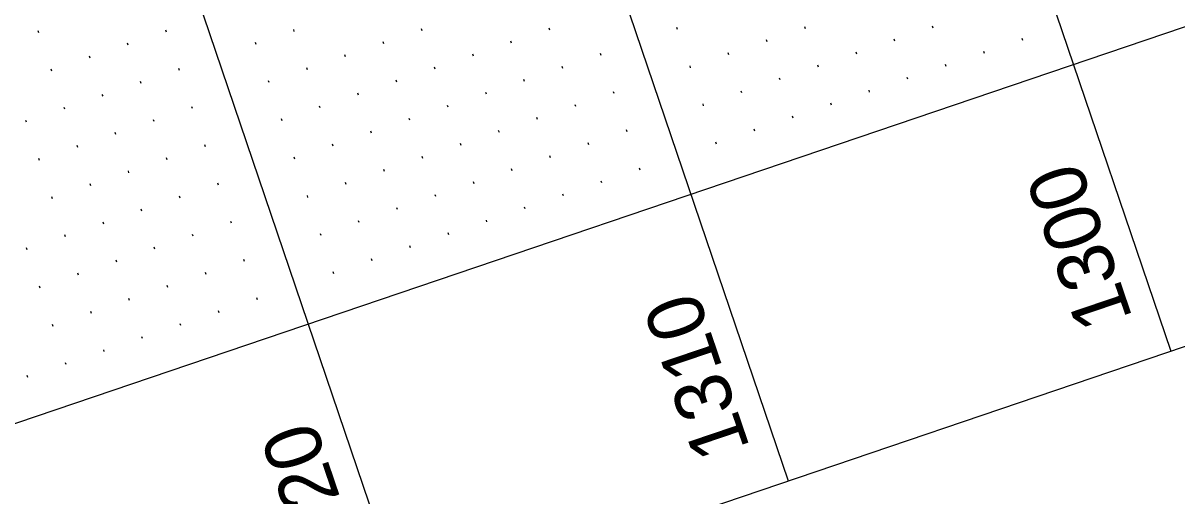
# Model space of a CAD drawing. Extents: x 2150800 to 2152547, y 141860 to 143950.
# Drawn here: x 2152030.1 to 2152172.8, y 142300.8 to 142359.4 of the extents above; entities that cross this region are included whole.
import ezdxf

# ---------------------------------------------------------------- set-up
doc = ezdxf.new("R2010")
doc.units = 0
for name, color, linetype in [('SHT_Plan_Profile_Sheet_Elev_Txt', 7, 'Continuous'), ('SHT_Profile_Grid_Major', 7, 'Continuous'), ('SHT_Profile_Grid_Minor', 7, 'Continuous'), ('SHT_Sheet_Border', 7, 'Continuous')]:
    doc.layers.add(name, color=color, linetype=linetype)

msp = doc.modelspace()

# ---------------------------------------------------------------- linework, layer by layer
at = {"layer": 'SHT_Profile_Grid_Major'}
for p, q in [((2152172.11, 142318.73), (2151666.12, 143810.24)), ((2152124.76, 142302.67), (2151618.77, 143794.18)), ((2152077.41, 142286.61), (2151571.42, 143778.12))]:
    msp.add_line(p, q, dxfattribs=at)
at = {"layer": 'SHT_Profile_Grid_Minor'}
for p, q in [((2152032.01, 142358.19), (2152031.93, 142358.43)), ((2152047.82, 142358.27), (2152047.74, 142358.51)), ((2152063.63, 142358.36), (2152063.55, 142358.59)), ((2152079.44, 142358.44), (2152079.36, 142358.68)), ((2152095.25, 142358.53), (2152095.17, 142358.76)), ((2152111.06, 142358.61), (2152110.98, 142358.85)), ((2152126.87, 142358.69), (2152126.79, 142358.93)), ((2152142.69, 142358.78), (2152142.61, 142359.01)), ((2152043.08, 142356.67), (2152043, 142356.9)), ((2152058.9, 142356.75), (2152058.81, 142356.99)), ((2152074.71, 142356.84), (2152074.63, 142357.07)), ((2152090.52, 142356.92), (2152090.44, 142357.16)), ((2152122.14, 142357.09), (2152122.06, 142357.32)), ((2152137.95, 142357.17), (2152137.87, 142357.41)), ((2152153.76, 142357.26), (2152153.68, 142357.49)), ((2152038.35, 142355.06), (2152038.27, 142355.3)), ((2152069.97, 142355.23), (2152069.89, 142355.47)), ((2152085.78, 142355.31), (2152085.7, 142355.55)), ((2152101.59, 142355.4), (2152101.51, 142355.63)), ((2152117.4, 142355.48), (2152117.32, 142355.72)), ((2152133.22, 142355.56), (2152133.14, 142355.8)), ((2152149.03, 142355.65), (2152148.95, 142355.89)), ((2152033.61, 142353.45), (2152033.53, 142353.69)), ((2152049.43, 142353.54), (2152049.34, 142353.78)), ((2152065.24, 142353.62), (2152065.16, 142353.86)), ((2152081.05, 142353.71), (2152080.97, 142353.94)), ((2152096.86, 142353.79), (2152096.78, 142354.03)), ((2152112.67, 142353.87), (2152112.59, 142354.11)), ((2152128.48, 142353.96), (2152128.4, 142354.2)), ((2152144.29, 142354.04), (2152144.21, 142354.28)), ((2152044.69, 142351.93), (2152044.61, 142352.17)), ((2152060.5, 142352.02), (2152060.42, 142352.25)), ((2152076.31, 142352.1), (2152076.23, 142352.34)), ((2152092.12, 142352.18), (2152092.04, 142352.42)), ((2152123.75, 142352.35), (2152123.67, 142352.59)), ((2152139.56, 142352.44), (2152139.48, 142352.67)), ((2152039.96, 142350.33), (2152039.87, 142350.56)), ((2152071.58, 142350.49), (2152071.5, 142350.73)), ((2152087.39, 142350.58), (2152087.31, 142350.81)), ((2152103.2, 142350.66), (2152103.12, 142350.9)), ((2152119.01, 142350.75), (2152118.93, 142350.98)), ((2152134.82, 142350.83), (2152134.74, 142351.07)), ((2152051.03, 142348.8), (2152050.95, 142349.04)), ((2152066.84, 142348.89), (2152066.76, 142349.12)), ((2152082.65, 142348.97), (2152082.57, 142349.21)), ((2152098.46, 142349.06), (2152098.38, 142349.29)), ((2152114.28, 142349.14), (2152114.2, 142349.38)), ((2152130.09, 142349.22), (2152130.01, 142349.46)), ((2152035.22, 142348.72), (2152035.14, 142348.96)), ((2152093.73, 142347.45), (2152093.65, 142347.69)), ((2152125.35, 142347.62), (2152125.27, 142347.85)), ((2152030.49, 142347.11), (2152030.41, 142347.35)), ((2152046.3, 142347.2), (2152046.22, 142347.43)), ((2152062.11, 142347.28), (2152062.03, 142347.52)), ((2152077.92, 142347.37), (2152077.84, 142347.6)), ((2152120.62, 142346.01), (2152120.54, 142346.25)), ((2152041.56, 142345.59), (2152041.48, 142345.83)), ((2152073.18, 142345.76), (2152073.1, 142346)), ((2152089, 142345.84), (2152088.91, 142346.08)), ((2152104.81, 142345.93), (2152104.73, 142346.16)), ((2152036.83, 142343.98), (2152036.75, 142344.22)), ((2152052.64, 142344.07), (2152052.56, 142344.31)), ((2152068.45, 142344.15), (2152068.37, 142344.39)), ((2152084.26, 142344.24), (2152084.18, 142344.47)), ((2152100.07, 142344.32), (2152099.99, 142344.56)), ((2152115.88, 142344.4), (2152115.8, 142344.64)), ((2152032.09, 142342.38), (2152032.01, 142342.62)), ((2152047.9, 142342.46), (2152047.82, 142342.7)), ((2152063.71, 142342.55), (2152063.63, 142342.78)), ((2152079.53, 142342.63), (2152079.44, 142342.87)), ((2152095.34, 142342.71), (2152095.26, 142342.95)), ((2152043.17, 142340.86), (2152043.09, 142341.09)), ((2152074.79, 142341.02), (2152074.71, 142341.26)), ((2152090.6, 142341.11), (2152090.52, 142341.34)), ((2152106.41, 142341.19), (2152106.33, 142341.43)), ((2152038.43, 142339.25), (2152038.35, 142339.49)), ((2152054.24, 142339.33), (2152054.16, 142339.57)), ((2152070.06, 142339.42), (2152069.98, 142339.65)), ((2152085.87, 142339.5), (2152085.79, 142339.74)), ((2152101.68, 142339.59), (2152101.6, 142339.82)), ((2152033.7, 142337.64), (2152033.62, 142337.88)), ((2152049.51, 142337.73), (2152049.43, 142337.96)), ((2152065.32, 142337.81), (2152065.24, 142338.05)), ((2152081.13, 142337.9), (2152081.05, 142338.13)), ((2152096.94, 142337.98), (2152096.86, 142338.22)), ((2152044.77, 142336.12), (2152044.69, 142336.36)), ((2152076.4, 142336.29), (2152076.32, 142336.53)), ((2152092.21, 142336.37), (2152092.13, 142336.61)), ((2152055.85, 142334.6), (2152055.77, 142334.84)), ((2152071.66, 142334.68), (2152071.58, 142334.92)), ((2152087.47, 142334.77), (2152087.39, 142335)), ((2152040.04, 142334.51), (2152039.96, 142334.75)), ((2152082.74, 142333.16), (2152082.66, 142333.4)), ((2152035.3, 142332.91), (2152035.22, 142333.15)), ((2152051.12, 142332.99), (2152051.04, 142333.23)), ((2152066.93, 142333.08), (2152066.85, 142333.31)), ((2152030.57, 142331.3), (2152030.49, 142331.54)), ((2152046.38, 142331.39), (2152046.3, 142331.62)), ((2152078, 142331.55), (2152077.92, 142331.79)), ((2152041.65, 142329.78), (2152041.57, 142330.02)), ((2152057.46, 142329.86), (2152057.38, 142330.1)), ((2152073.27, 142329.95), (2152073.19, 142330.18)), ((2152036.91, 142328.17), (2152036.83, 142328.41)), ((2152052.72, 142328.26), (2152052.64, 142328.49)), ((2152068.53, 142328.34), (2152068.45, 142328.58)), ((2152032.18, 142326.57), (2152032.1, 142326.8)), ((2152047.99, 142326.65), (2152047.91, 142326.89)), ((2152043.25, 142325.04), (2152043.17, 142325.28)), ((2152059.06, 142325.13), (2152058.98, 142325.37)), ((2152038.52, 142323.44), (2152038.44, 142323.68)), ((2152054.33, 142323.52), (2152054.25, 142323.76)), ((2152033.78, 142321.83), (2152033.7, 142322.07)), ((2152049.59, 142321.92), (2152049.51, 142322.15)), ((2152044.86, 142320.31), (2152044.78, 142320.55)), ((2152040.12, 142318.7), (2152040.04, 142318.94)), ((2152035.39, 142317.1), (2152035.31, 142317.33)), ((2152030.65, 142315.49), (2152030.57, 142315.73))]:
    msp.add_line(p, q, dxfattribs=at)
at = {"layer": 'SHT_Sheet_Border'}
msp.add_line((2152349.46, 142418.5), (2151875.97, 142257.87), dxfattribs=at)
msp.add_lwpolyline([(2151383.74, 142051.28), (2150877.75, 143542.79), (2151872.09, 143880.12), (2152378.08, 142388.61)], close=True, dxfattribs=at)

# ---------------------------------------------------------------- texts
at = {"layer": 'SHT_Plan_Profile_Sheet_Elev_Txt'}
for s, p in [('1300', (2152167.39, 142322.83)), ('1310', (2152120.04, 142306.76)), ('1320', (2152072.69, 142290.7))]:
    msp.add_text(s, height=7, rotation=108.7393, dxfattribs=at).set_placement(p)

doc.saveas('drawing.dxf')
